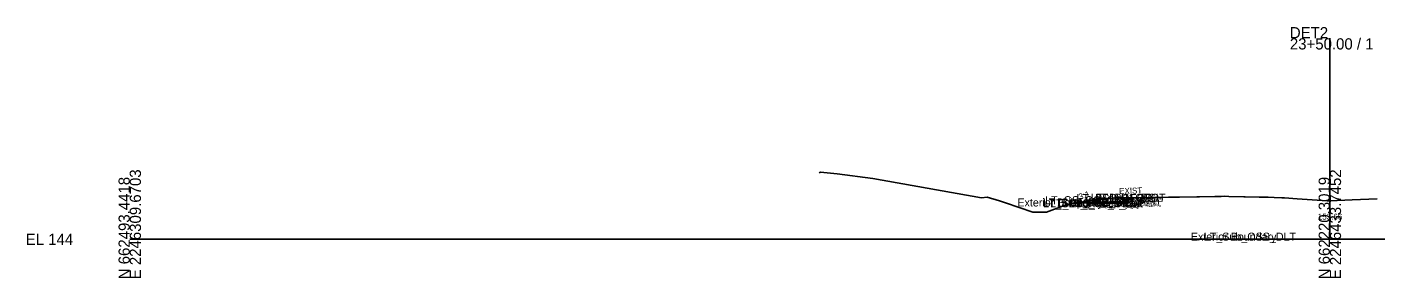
# Model space of a CAD drawing. Extents: x -26 to 603, y -10 to 9526.
# Drawn here: x -25.7 to 311.3, y 6490.3 to 6553.1 of the extents above; entities that cross this region are included whole.
import ezdxf

# ---------------------------------------------------------------- set-up
doc = ezdxf.new("R2010")
doc.units = 0
for name, color, linetype in [('Default', 7, 'Continuous'), ('Exist Cross Section Cell', 7, 'Continuous'), ('Exist XS Center Line Elevation Label', 7, 'Continuous'), ('Exist XS Ground Line', 7, 'Continuous'), ('Prop CMT Pvmt Course 1', 7, 'Continuous'), ('Prop CMT Pvmt Course 2', 7, 'Continuous'), ('Prop CMT Pvmt Course 3', 7, 'Continuous'), ('Prop CMT Pvmt Surface', 7, 'Continuous'), ('Prop CMT Pvmt Surface Shoulder', 7, 'Continuous'), ('Prop CMT Shld Paved Course 1', 7, 'Continuous'), ('Prop CMT Shld Paved Course 2', 7, 'Continuous'), ('Prop CMT Shld Paved Course 3', 7, 'Continuous'), ('Prop CMT Slope Grass', 7, 'Continuous'), ('Prop CMT Subgrade Earthwork', 7, 'Continuous'), ('Prop XS SE Text', 7, 'Continuous'), ('Prop XS Side Slope Text', 7, 'Continuous'), ('Scratch_Level_2', 7, 'Continuous')]:
    doc.layers.add(name, color=color, linetype=linetype)

msp = doc.modelspace()

# ---------------------------------------------------------------- linework, layer by layer
at = {"layer": 'Exist Cross Section Cell'}
for p, q in [((300, 6500), (300, 6550.27)), ((0, 6500), (300, 6500)), ((300, 6500), (600, 6500))]:
    msp.add_line(p, q, dxfattribs=at)
at = {"layer": 'Exist XS Ground Line'}
for p, q in [((172.32, 6516.66), (172.68, 6516.76)), ((172.68, 6516.76), (176.84, 6516.35)), ((176.84, 6516.35), (185.72, 6515.18)), ((185.72, 6515.18), (212.91, 6510.38)), ((266.77, 6510.61), (267.38, 6510.61)), ((267.38, 6510.61), (271.24, 6510.69)), ((271.24, 6510.69), (272.79, 6510.72)), ((272.79, 6510.72), (273.65, 6510.75)), ((273.65, 6510.75), (274.74, 6510.68)), ((274.74, 6510.68), (278.52, 6510.61)), ((212.91, 6510.38), (214.3, 6510.5)), ((214.3, 6510.5), (217.43, 6509.63)), ((217.43, 6509.63), (218.93, 6509.09)), ((218.93, 6509.09), (225.75, 6506.75)), ((229.13, 6506.82), (233.85, 6508.5)), ((233.85, 6508.5), (234.91, 6508.85)), ((234.91, 6508.85), (237.64, 6509.19)), ((237.64, 6509.19), (246.5, 6510.38)), ((246.5, 6510.38), (249.73, 6510.39)), ((249.73, 6510.39), (250.95, 6510.41)), ((250.95, 6510.41), (254.68, 6510.46)), ((254.68, 6510.46), (255.86, 6510.48)), ((255.86, 6510.48), (256.4, 6510.48)), ((256.4, 6510.48), (259.64, 6510.52)), ((259.64, 6510.52), (259.95, 6510.53)), ((259.95, 6510.53), (261.23, 6510.55)), ((261.23, 6510.55), (261.67, 6510.56)), ((261.67, 6510.56), (262.38, 6510.56)), ((262.38, 6510.56), (266.77, 6510.61)), ((278.52, 6510.61), (278.86, 6510.6)), ((278.86, 6510.6), (282.29, 6510.54)), ((282.29, 6510.54), (282.93, 6510.52)), ((282.93, 6510.52), (284.59, 6510.52)), ((284.59, 6510.52), (286.07, 6510.45)), ((286.07, 6510.45), (288, 6510.37)), ((288, 6510.37), (288.68, 6510.34)), ((288.68, 6510.34), (291.85, 6510.13)), ((291.85, 6510.13), (299.33, 6509.64)), ((299.33, 6509.64), (300, 6509.66)), ((300, 6509.66), (305.54, 6509.85)), ((305.54, 6509.85), (311.85, 6510.08)), ((225.75, 6506.75), (228.47, 6506.8)), ((228.47, 6506.8), (229.13, 6506.82))]:
    msp.add_line(p, q, dxfattribs=at)
at = {"layer": 'Prop CMT Pvmt Course 1'}
for points in [[(249.73, 6510.39), (249.47, 6510.38)], [(249.47, 6510.38), (249.47, 6509.47)], [(249.47, 6509.47), (249.73, 6509.47)], [(249.73, 6509.47), (249.73, 6510.39)]]:
    msp.add_lwpolyline(points, dxfattribs=at)
at = {"layer": 'Prop CMT Pvmt Course 2'}
for points in [[(249.73, 6509.47), (249.47, 6509.47)], [(249.47, 6509.47), (249.47, 6509.13)], [(249.47, 6509.13), (249.73, 6509.14)], [(249.73, 6509.14), (249.73, 6509.47)]]:
    msp.add_lwpolyline(points, dxfattribs=at)
at = {"layer": 'Prop CMT Pvmt Course 3'}
for points in [[(249.73, 6509.14), (249.47, 6509.13)], [(249.47, 6509.13), (249.73, 6509.14)], [(249.47, 6509.13), (249.47, 6509.13)], [(249.73, 6509.14), (249.73, 6509.14)]]:
    msp.add_lwpolyline(points, dxfattribs=at)
at = {"layer": 'Prop CMT Pvmt Surface'}
msp.add_lwpolyline([(249.73, 6510.39), (249.47, 6510.38)], dxfattribs=at)
at = {"layer": 'Prop CMT Pvmt Surface Shoulder'}
msp.add_lwpolyline([(249.47, 6510.38), (245.88, 6510.29)], dxfattribs=at)
at = {"layer": 'Prop CMT Shld Paved Course 1'}
for points in [[(249.47, 6510.38), (245.88, 6510.29), (244.94, 6509.35)], [(244.94, 6509.35), (249.47, 6509.47)], [(249.47, 6509.47), (249.47, 6510.38)]]:
    msp.add_lwpolyline(points, dxfattribs=at)
at = {"layer": 'Prop CMT Shld Paved Course 2'}
for points in [[(249.47, 6509.47), (244.94, 6509.35), (244.59, 6509.01)], [(244.59, 6509.01), (249.47, 6509.13)], [(249.47, 6509.13), (249.47, 6509.47)]]:
    msp.add_lwpolyline(points, dxfattribs=at)
at = {"layer": 'Prop CMT Shld Paved Course 3'}
for points in [[(249.47, 6509.13), (244.59, 6509.01), (244.09, 6509)], [(244.09, 6509), (249.47, 6509.13)], [(244.09, 6509), (244.09, 6509)], [(249.47, 6509.13), (249.47, 6509.13)]]:
    msp.add_lwpolyline(points, dxfattribs=at)
at = {"layer": 'Prop CMT Slope Grass'}
msp.add_lwpolyline([(245.88, 6510.29), (239.47, 6509.78), (237.75, 6509.21)], dxfattribs=at)
at = {"layer": 'Prop CMT Subgrade Earthwork'}
for points in [[(244.09, 6509), (237.75, 6509.21)], [(249.47, 6509.13), (244.09, 6509)], [(249.73, 6509.14), (249.47, 6509.13)]]:
    msp.add_lwpolyline(points, dxfattribs=at)

# ---------------------------------------------------------------- texts
at = {"layer": 'Default'}
msp.add_text('-', height=0.0001, dxfattribs=at).set_placement((0, 6500))
msp.add_text('-', height=0.0001, dxfattribs=at).set_placement((0, 6500))
msp.add_text('-', height=0.0001, dxfattribs=at).set_placement((0, 6500))
msp.add_text('-', height=0.0001, dxfattribs=at).set_placement((0, 6500))
at = {"layer": 'Exist Cross Section Cell'}
for s, p in [('DET2', (290, 6550.27)), ('23+50.00 / 1', (290, 6547.47)), ('EL 144', (-26, 6498.6))]:
    msp.add_text(s, height=2.8, dxfattribs=at).set_placement(p)
for s, p in [('N 662493.4418', (0, 6490)), ('E 2246309.6703', (2.8, 6490)), ('N 662220.3019', (300, 6490)), ('E 2246433.7452', (302.8, 6490))]:
    msp.add_text(s, height=2.8, rotation=90, dxfattribs=at).set_placement(p)
at = {"layer": 'Exist XS Center Line Elevation Label'}
msp.add_text('153.66', height=1.5, dxfattribs=at).set_placement((296.98, 6504.91))
at = {"layer": 'Prop XS SE Text'}
msp.add_text('EXIST', height=1.5, rotation=1.4321, dxfattribs=at).set_placement((247.33, 6511.33))
at = {"layer": 'Prop XS Side Slope Text'}
msp.add_text('3:1', height=1.5, rotation=18.4332, dxfattribs=at).set_placement((237.5, 6509.86))
at = {"layer": 'Scratch_Level_2'}
for s, p in [('LT_GS_OS_CTL', (228.84, 6508.78)), ('LT_PS1_OEOP', (236.68, 6509.29)), ('LT_PV1_OEOT', (240.21, 6509.38)), ('LT_PV1_PGL', (241.51, 6509.39)), ('Exterior Boundary', (221.89, 6508.21)), ('LT_Slope_Fill', (228.27, 6508.21)), ('LT_Sub_Trench_Out', (228.3, 6508)), ('LT_PS3_Shelf_Out', (230.08, 6508)), ('LT_PS3_OEOP', (234.83, 6508.01)), ('LT_PS2_OEOP', (235.17, 6508.35)), ('LT_Sub_OEOT', (239.55, 6508.13)), ('LT_PV2_OEOT', (239.65, 6508.47)), ('LT_PV3_OEOT', (239.65, 6508.13)), ('LT_Sub_PGL', (240.85, 6508.14)), ('LT_PV2_PGL', (240.94, 6508.47)), ('LT_PV3_PGL', (240.94, 6508.14)), ('Exterior Boundary', (265.25, 6499.66)), ('Exterior Boundary', (265.25, 6499.66)), ('LT_Sub_OSS_DLT', (268.51, 6499.66)), ('LT_Sub_OSS_DLT', (268.51, 6499.66))]:
    msp.add_text(s, height=2, dxfattribs=at).set_placement(p)

doc.saveas('drawing.dxf')
